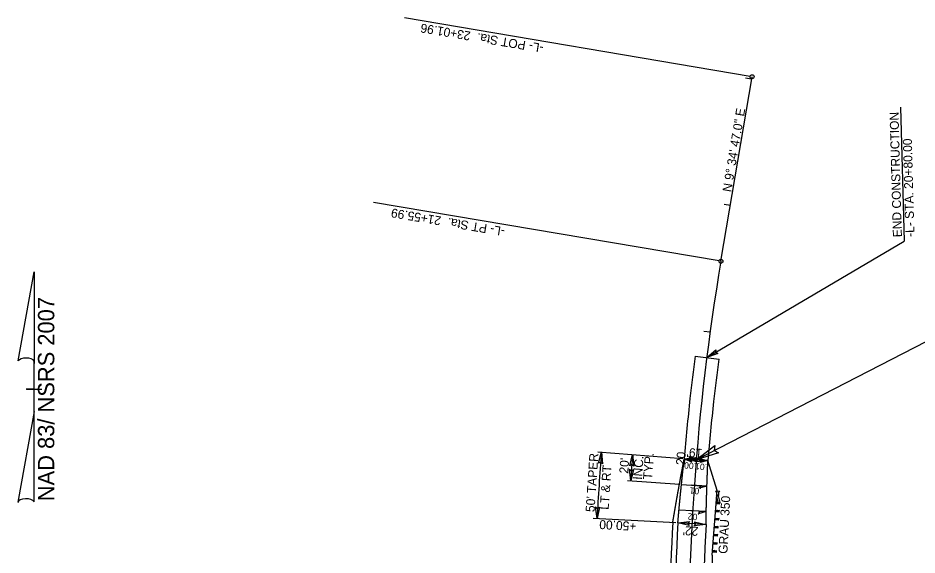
# Model space of a CAD drawing. Extents: x 1835351 to 1836442, y 993887 to 995358.
# Drawn here: x 1835358 to 1836059, y 994883 to 995302 of the extents above; entities that cross this region are included whole.
import ezdxf

# ---------------------------------------------------------------- set-up
doc = ezdxf.new("R2010")
doc.units = 0
for name, color, linetype in [('Prop Dimension', 7, 'Continuous'), ('Prop Dimension Text', 7, 'Continuous'), ('Prop EOT', 7, 'Continuous'), ('Prop Guardrail', 7, 'Continuous'), ('Prop Guardrail Anchor Unit CELL', 7, 'Continuous'), ('Prop Horizontal Alignment', 7, 'Continuous'), ('Prop Horizontal Alignment Direction Label', 7, 'Continuous'), ('Prop Horizontal Alignment Station Label', 7, 'Continuous'), ('Prop Horizontal Alignment Tick Label', 7, 'Continuous'), ('Prop Horizontal Alignment Tick Large', 7, 'Continuous'), ('Prop Horizontal Alignment Tick Small', 7, 'Continuous'), ('Prop Lane Lines', 7, 'Continuous'), ('Prop North Arrow NAD83 for Plan Sheets CELL', 7, 'Continuous'), ('Prop Paved Shoulder', 7, 'Continuous'), ('Prop Superelevation  Arrow CELL', 7, 'Continuous'), ('Prop Superelevation Label', 7, 'Continuous'), ('Prop Terminator CELL', 7, 'Continuous')]:
    doc.layers.add(name, color=color, linetype=linetype)

msp = doc.modelspace()

# ---------------------------------------------------------------- linework, layer by layer
at = {"layer": 'Prop Dimension'}
for p, q in [((1836046.57, 995232.25), (1836049.43, 995127.52)), ((1835895.31, 995036.81), (1836049.43, 995127.52)), ((1835810.24, 994963.48), (1835876.57, 994958.09)), ((1835877.74, 994958), (1835896.2, 994956.5)), ((1835833.43, 994940.95), (1835874.1, 994938.1)), ((1835871.15, 994908.03), (1835806.69, 994911.47)), ((1835894.7, 994906.77), (1835872.73, 994907.94))]:
    msp.add_line(p, q, dxfattribs=at)
for radius, end in [(1884.18, 176.94086), (1859.77, 175.99121)]:
    msp.add_arc((1837691.14, 994810.76), radius, 175.35811, end, dxfattribs=at)
at = {"layer": 'Prop Dimension Text'}
msp.add_line((1835887.07, 994957.24), (1836077.4, 995055.09), dxfattribs=at)
at = {"layer": 'Prop EOT'}
msp.add_line((1835886.28, 995037.95), (1835904.85, 995035.61), dxfattribs=at)
for radius in [1821, 1799]:
    msp.add_arc((1837691.14, 994810.76), radius, 176.94086, 181.53384, dxfattribs=at)
for centre, major_axis, ratio, start_param, end_param in [((1837192.63, 994942.7), (-342.09, -1896.88), 0.677504, 4.78411, 4.801345), ((1838782.69, 994796.91), (-746.07, -3717.17), 0.759534, 4.800145, 4.808919), ((1837641.28, 994819), (-1537.35, -877.61), 0.997858, 5.658085, 5.684815), ((1837572.45, 994795.61), (212.83, -1723.77), 0.968108, 4.473864, 4.500611)]:
    msp.add_ellipse(centre, major_axis=major_axis, ratio=ratio, start_param=start_param, end_param=end_param, dxfattribs=at)
for points in [[(1835872.73, 994907.94), (1835872.79, 994908.62), (1835872.85, 994909.3), (1835872.91, 994909.98), (1835872.97, 994910.65), (1835873.03, 994911.33), (1835873.09, 994912.01), (1835873.15, 994912.69), (1835873.21, 994913.36), (1835873.27, 994914.04), (1835873.33, 994914.72), (1835873.39, 994915.39), (1835873.45, 994916.07), (1835873.51, 994916.75), (1835873.57, 994917.43), (1835873.64, 994918.1), (1835873.7, 994918.78), (1835873.76, 994919.46), (1835873.82, 994920.13), (1835873.89, 994920.81), (1835873.95, 994921.49), (1835874.01, 994922.17), (1835874.08, 994922.84), (1835874.14, 994923.52), (1835874.21, 994924.2), (1835874.27, 994924.87), (1835874.33, 994925.55), (1835874.4, 994926.23), (1835874.46, 994926.9), (1835874.53, 994927.58), (1835874.6, 994928.26), (1835874.66, 994928.93), (1835874.73, 994929.61), (1835874.8, 994930.29), (1835874.86, 994930.96), (1835874.93, 994931.64), (1835875, 994932.32), (1835875.06, 994932.99), (1835875.13, 994933.67), (1835875.2, 994934.35), (1835875.27, 994935.02), (1835875.34, 994935.7), (1835875.41, 994936.38), (1835875.48, 994937.05), (1835875.54, 994937.73), (1835875.61, 994938.4), (1835875.68, 994939.08), (1835875.75, 994939.76), (1835875.82, 994940.43), (1835875.9, 994941.11), (1835875.97, 994941.78), (1835876.04, 994942.46), (1835876.11, 994943.14), (1835876.18, 994943.81), (1835876.25, 994944.49), (1835876.32, 994945.16), (1835876.4, 994945.84), (1835876.47, 994946.52), (1835876.54, 994947.19), (1835876.62, 994947.87), (1835876.69, 994948.54), (1835876.76, 994949.22), (1835876.84, 994949.89), (1835876.91, 994950.57), (1835876.99, 994951.25), (1835877.06, 994951.92), (1835877.13, 994952.6), (1835877.21, 994953.27), (1835877.29, 994953.95), (1835877.36, 994954.62), (1835877.44, 994955.3), (1835877.51, 994955.97), (1835877.59, 994956.65), (1835877.74, 994958)], [(1835894.7, 994906.77), (1835894.71, 994907.44), (1835894.72, 994908.11), (1835894.73, 994908.78), (1835894.75, 994909.46), (1835894.76, 994910.13), (1835894.77, 994910.8), (1835894.78, 994911.47), (1835894.79, 994912.14), (1835894.81, 994912.82), (1835894.82, 994913.49), (1835894.83, 994914.16), (1835894.85, 994914.83), (1835894.86, 994915.5), (1835894.88, 994916.18), (1835894.89, 994916.85), (1835894.91, 994917.52), (1835894.92, 994918.19), (1835894.94, 994918.86), (1835894.95, 994919.54), (1835894.97, 994920.21), (1835894.98, 994920.88), (1835895, 994921.55), (1835895.02, 994922.22), (1835895.03, 994922.9), (1835895.05, 994923.57), (1835895.07, 994924.24), (1835895.09, 994924.91), (1835895.1, 994925.58), (1835895.12, 994926.26), (1835895.14, 994926.93), (1835895.16, 994927.6), (1835895.18, 994928.27), (1835895.2, 994928.94), (1835895.22, 994929.62), (1835895.24, 994930.29), (1835895.26, 994930.96), (1835895.28, 994931.63), (1835895.3, 994932.31), (1835895.32, 994932.98), (1835895.34, 994933.65), (1835895.36, 994934.32), (1835895.38, 994934.99), (1835895.4, 994935.67), (1835895.42, 994936.34), (1835895.45, 994937.01), (1835895.47, 994937.68), (1835895.49, 994938.35), (1835895.51, 994939.03), (1835895.54, 994939.7), (1835895.56, 994940.37), (1835895.58, 994941.04), (1835895.61, 994941.71), (1835895.63, 994942.39), (1835895.66, 994943.06), (1835895.68, 994943.73), (1835895.71, 994944.4), (1835895.73, 994945.07), (1835895.76, 994945.75), (1835895.78, 994946.42), (1835895.81, 994947.09), (1835895.83, 994947.76), (1835895.86, 994948.44), (1835895.89, 994949.11), (1835895.91, 994949.78), (1835895.94, 994950.45), (1835895.97, 994951.12), (1835896, 994951.8), (1835896.02, 994952.47), (1835896.05, 994953.14), (1835896.08, 994953.81), (1835896.11, 994954.48), (1835896.14, 994955.16), (1835896.2, 994956.5)]]:
    msp.add_spline(points, degree=3, dxfattribs=at)
at = {"layer": 'Prop Guardrail'}
msp.add_arc((1837691.14, 994810.76), 1793, 177.69413, 180.25074, dxfattribs=at)
at = {"layer": 'Prop Guardrail Anchor Unit CELL'}
for p, q in [((1835899.59, 994882.9), (1835903.05, 994929.52)), ((1835903.24, 994931.6), (1835902.45, 994932.82)), ((1835902.45, 994932.82), (1835905.39, 994932.65)), ((1835904.59, 994929.91), (1835903.02, 994929.03)), ((1835903.02, 994929.03), (1835904.51, 994928.92)), ((1835904.18, 994924.03), (1835903.02, 994929.03)), ((1835903.09, 994930.02), (1835904.59, 994929.91)), ((1835903.09, 994930.02), (1835904.51, 994928.92)), ((1835903.13, 994929.55), (1835903.24, 994931.6)), ((1835903.74, 994929.52), (1835903.13, 994929.55)), ((1835904.35, 994929.48), (1835903.74, 994929.52)), ((1835904.46, 994931.53), (1835904.35, 994929.48)), ((1835905.39, 994932.65), (1835904.46, 994931.53)), ((1835904.51, 994928.92), (1835904.59, 994929.91)), ((1835904.51, 994928.92), (1835904.55, 994929.41)), ((1835905.71, 994923.91), (1835904.51, 994928.92)), ((1835902.58, 994923.14), (1835904.18, 994924.03)), ((1835902.58, 994923.14), (1835905.63, 994922.91)), ((1835902.65, 994924.14), (1835905.71, 994923.91)), ((1835904.11, 994923.03), (1835902.65, 994924.14)), ((1835904.11, 994923.03), (1835904.18, 994924.03)), ((1835905.71, 994923.91), (1835904.11, 994923.03)), ((1835904.18, 994924.03), (1835905.63, 994922.91)), ((1835905.63, 994922.91), (1835905.71, 994923.91)), ((1835902.11, 994916.86), (1835903.68, 994917.74)), ((1835902.11, 994916.86), (1835905.1, 994916.64)), ((1835902.19, 994917.85), (1835905.18, 994917.63)), ((1835903.61, 994916.75), (1835902.19, 994917.85)), ((1835903.61, 994916.75), (1835903.68, 994917.74)), ((1835905.18, 994917.63), (1835903.61, 994916.75)), ((1835903.68, 994917.74), (1835905.1, 994916.64)), ((1835905.1, 994916.64), (1835905.18, 994917.63)), ((1835901.64, 994910.57), (1835903.28, 994911.45)), ((1835901.64, 994910.57), (1835904.77, 994910.34)), ((1835901.72, 994911.57), (1835904.85, 994911.34)), ((1835903.21, 994910.46), (1835901.72, 994911.57)), ((1835903.21, 994910.46), (1835903.28, 994911.45)), ((1835904.85, 994911.34), (1835903.21, 994910.46)), ((1835903.28, 994911.45), (1835904.77, 994910.34)), ((1835904.77, 994910.34), (1835904.85, 994911.34)), ((1835901.18, 994904.29), (1835901.25, 994905.29)), ((1835901.18, 994904.29), (1835902.77, 994905.17)), ((1835901.18, 994904.29), (1835904.2, 994904.06)), ((1835901.25, 994905.29), (1835904.28, 994905.06)), ((1835902.69, 994904.18), (1835901.25, 994905.29)), ((1835902.69, 994904.18), (1835902.77, 994905.17)), ((1835904.28, 994905.06), (1835902.69, 994904.18)), ((1835902.77, 994905.17), (1835904.2, 994904.06)), ((1835904.2, 994904.06), (1835904.28, 994905.06)), ((1835900.71, 994898.01), (1835902.3, 994898.89)), ((1835900.71, 994898.01), (1835903.75, 994897.78)), ((1835900.78, 994899), (1835903.82, 994898.78)), ((1835902.23, 994897.89), (1835900.78, 994899)), ((1835902.23, 994897.89), (1835902.3, 994898.89)), ((1835903.82, 994898.78), (1835902.23, 994897.89)), ((1835902.3, 994898.89), (1835903.75, 994897.78)), ((1835903.75, 994897.78), (1835903.82, 994898.78)), ((1835899.78, 994885.44), (1835899.85, 994886.44)), ((1835901.35, 994886.32), (1835899.78, 994885.44)), ((1835899.85, 994886.44), (1835902.84, 994886.21)), ((1835899.85, 994886.44), (1835901.35, 994886.32)), ((1835901.27, 994885.33), (1835899.85, 994886.44)), ((1835900.24, 994891.72), (1835901.84, 994892.61)), ((1835900.24, 994891.72), (1835903.29, 994891.5)), ((1835900.32, 994892.72), (1835903.36, 994892.49)), ((1835901.77, 994891.61), (1835900.32, 994892.72)), ((1835901.27, 994885.33), (1835901.35, 994886.32)), ((1835902.84, 994886.21), (1835901.27, 994885.33)), ((1835901.35, 994886.32), (1835902.77, 994885.22)), ((1835901.77, 994891.61), (1835901.84, 994892.61)), ((1835903.36, 994892.49), (1835901.77, 994891.61)), ((1835901.84, 994892.61), (1835903.29, 994891.5)), ((1835902.77, 994885.22), (1835902.84, 994886.21)), ((1835903.29, 994891.5), (1835903.36, 994892.49)), ((1835899.78, 994885.44), (1835902.77, 994885.22))]:
    msp.add_line(p, q, dxfattribs=at)
at = {"layer": 'Prop Horizontal Alignment'}
msp.add_line((1835906.38, 995111.98), (1835930.67, 995255.92), dxfattribs=at)
msp.add_arc((1837691.14, 994810.76), 1810, 170.42027, 181.53384, dxfattribs=at)
at = {"layer": 'Prop Horizontal Alignment Station Label'}
for p, q in [((1835929.19, 995256.17), (1835659.5, 995301.69)), ((1835904.9, 995112.23), (1835635.21, 995157.75))]:
    msp.add_line(p, q, dxfattribs=at)
for centre in [(1835930.67, 995255.92), (1835906.38, 995111.98)]:
    msp.add_circle(centre, 1.5, dxfattribs=at)
at = {"layer": 'Prop Horizontal Alignment Tick Large'}
msp.add_line((1835887.07, 994957.24), (1835879.1, 994957.89), dxfattribs=at)
at = {"layer": 'Prop Horizontal Alignment Tick Small'}
for p, q in [((1835930.34, 995253.99), (1835925.41, 995254.82)), ((1835913.7, 995155.38), (1835908.77, 995156.21)), ((1835897.91, 995056.64), (1835892.96, 995057.32))]:
    msp.add_line(p, q, dxfattribs=at)
at = {"layer": 'Prop North Arrow NAD83 for Plan Sheets CELL'}
for p, q in [((1835357.9, 995034.31), (1835370.23, 995103.83)), ((1835370.3, 995103.83), (1835370.23, 995103.83)), ((1835370.3, 995103.83), (1835370.23, 995103.83)), ((1835370.3, 995103.83), (1835370.28, 995032.13)), ((1835370.26, 994994.93), (1835370.28, 995034.23)), ((1835370.28, 995032.13), (1835370.28, 995034.16)), ((1835364.27, 995012.33), (1835364.2, 995012.33)), ((1835369.6, 995012.33), (1835364.27, 995012.33)), ((1835364.35, 995012.33), (1835376.35, 995012.33)), ((1835370.26, 994994.93), (1835357.71, 994924.06)), ((1835370.31, 994924.36), (1835370.26, 994994.93))]:
    msp.add_line(p, q, dxfattribs=at)
for centre, start_param, end_param in [((1835364.11, 995033.56), 0.216388, 2.908219), ((1835364.07, 994923.81), 0.201328, 3.141593)]:
    msp.add_ellipse(centre, major_axis=(6.34, -0.05), ratio=0.461098, start_param=start_param, end_param=end_param, dxfattribs=at)
at = {"layer": 'Prop Paved Shoulder'}
for p, q in [((1835903.33, 994933.25), (1835896.2, 994956.5)), ((1835899.59, 994882.9), (1835903.33, 994933.25))]:
    msp.add_line(p, q, dxfattribs=at)
for centre, radius, start, end in [((1837691.14, 994810.76), 1825, 176.94086, 180.92604), ((1837680.42, 994810.95), 1782.29, 177.68644, 180.25842)]:
    msp.add_arc(centre, radius, start, end, dxfattribs=at)
msp.add_spline([(1835868.74, 994908.16), (1835868.85, 994908.83), (1835868.96, 994909.51), (1835869.07, 994910.18), (1835869.19, 994910.86), (1835869.3, 994911.54), (1835869.42, 994912.21), (1835869.53, 994912.89), (1835869.64, 994913.56), (1835869.76, 994914.24), (1835869.87, 994914.91), (1835869.99, 994915.59), (1835870.1, 994916.27), (1835870.22, 994916.94), (1835870.34, 994917.62), (1835870.45, 994918.29), (1835870.57, 994918.97), (1835870.68, 994919.64), (1835870.8, 994920.32), (1835870.92, 994920.99), (1835871.04, 994921.67), (1835871.15, 994922.34), (1835871.27, 994923.02), (1835871.39, 994923.69), (1835871.51, 994924.37), (1835871.63, 994925.04), (1835871.75, 994925.71), (1835871.86, 994926.39), (1835871.98, 994927.06), (1835872.1, 994927.74), (1835872.22, 994928.41), (1835872.34, 994929.09), (1835872.46, 994929.76), (1835872.58, 994930.43), (1835872.7, 994931.11), (1835872.83, 994931.78), (1835872.95, 994932.45), (1835873.07, 994933.13), (1835873.19, 994933.8), (1835873.31, 994934.47), (1835873.44, 994935.15), (1835873.56, 994935.82), (1835873.68, 994936.49), (1835873.8, 994937.17), (1835873.93, 994937.84), (1835874.05, 994938.51), (1835874.17, 994939.19), (1835874.3, 994939.86), (1835874.42, 994940.53), (1835874.55, 994941.21), (1835874.67, 994941.88), (1835874.8, 994942.55), (1835874.92, 994943.22), (1835875.05, 994943.9), (1835875.17, 994944.57), (1835875.3, 994945.24), (1835875.43, 994945.91), (1835875.55, 994946.58), (1835875.68, 994947.26), (1835875.81, 994947.93), (1835875.93, 994948.6), (1835876.06, 994949.27), (1835876.19, 994949.94), (1835876.32, 994950.62), (1835876.45, 994951.29), (1835876.57, 994951.96), (1835876.7, 994952.63), (1835876.83, 994953.3), (1835876.96, 994953.97), (1835877.09, 994954.64), (1835877.22, 994955.31), (1835877.35, 994955.99), (1835877.48, 994956.66), (1835877.74, 994958)], degree=3, dxfattribs=at)
at = {"layer": 'Prop Superelevation  Arrow CELL'}
for p, q in [((1835877.74, 994958), (1835889.7, 994957.03)), ((1835887.07, 994957.24), (1835877.74, 994958)), ((1835896.2, 994956.5), (1835884.24, 994957.47)), ((1835895.43, 994936.61), (1835883.46, 994937.45)), ((1835894.89, 994916.71), (1835882.91, 994917.42))]:
    msp.add_line(p, q, dxfattribs=at)
for points in [[(1835877.74, 994958), (1835883.56, 994955.52), (1835882.35, 994957.62)], [(1835887.07, 994957.24), (1835881.25, 994959.72), (1835882.46, 994957.62)], [(1835896.2, 994956.5), (1835890.06, 994954.99), (1835891.59, 994956.87)], [(1835895.43, 994936.61), (1835889.31, 994935.03), (1835890.82, 994936.93)], [(1835894.89, 994916.71), (1835888.78, 994915.07), (1835890.27, 994916.99)]]:
    msp.add_lwpolyline(points, close=True, dxfattribs=at)
at = {"layer": 'Prop Superelevation Label'}
for p, q in [((1835875.57, 994938), (1835895.43, 994936.61)), ((1835894.89, 994916.71), (1835873.62, 994917.97))]:
    msp.add_line(p, q, dxfattribs=at)
at = {"layer": 'Prop Terminator CELL'}
for points in [[(1835903.85, 995040.04), (1835895.31, 995036.81), (1835902.29, 995042.78), (1835902.11, 995040.82)], [(1835904.5, 994962.71), (1835887.07, 994957.24), (1835901.71, 994968.36), (1835901.12, 994964.46)], [(1835810.87, 994954.4), (1835813.14, 994963.24), (1835814, 994954.09), (1835812.5, 994955.37)], [(1835835.19, 994952.42), (1835837.46, 994961.27), (1835838.32, 994952.12), (1835836.82, 994953.4)], [(1835886.59, 994955.73), (1835877.74, 994958), (1835886.89, 994958.86), (1835885.62, 994957.36)], [(1835887.35, 994958.77), (1835896.2, 994956.5), (1835887.05, 994955.64), (1835888.32, 994957.14)], [(1835838.09, 994949.65), (1835835.91, 994940.78), (1835834.95, 994949.92), (1835836.46, 994948.66)], [(1835811.67, 994920.22), (1835809.64, 994911.31), (1835808.53, 994920.44), (1835810.06, 994919.2)], [(1835881.64, 994905.91), (1835872.73, 994907.94), (1835881.85, 994909.06), (1835880.62, 994907.52)], [(1835885.79, 994908.8), (1835894.7, 994906.77), (1835885.58, 994905.65), (1835886.81, 994907.19)]]:
    msp.add_lwpolyline(points, close=True, dxfattribs=at)

# ---------------------------------------------------------------- texts
at = {"layer": 'Prop Dimension Text'}
for s, rotation, p in [('END CONSTRUCTION', 91.56434, (1836047.63, 995130.81)), ('-L- STA. 20+80.00', 91.56434, (1836057.42, 995131.07)), ("50' TAPER", 86.14949, (1835807.67, 994916.21)), ("20'", 85.67466, (1835833.92, 994946.17)), ('INC.', 85.67466, (1835844.62, 994941.36)), ('TYP.', 85.67466, (1835852.52, 994941.54)), ('LT & RT', 86.14949, (1835818.68, 994918)), ('+50.00', 176.94086, (1835840.5, 994908.65))]:
    msp.add_text(s, height=7, rotation=rotation, dxfattribs=at).set_placement(p)
at = {"layer": 'Prop Guardrail Anchor Unit CELL'}
msp.add_text('GRAU 350', height=7, rotation=87.08342, dxfattribs=at).set_placement((1835911.36, 994883.69))
at = {"layer": 'Prop Horizontal Alignment Direction Label'}
msp.add_text('N 9%%d 34\' 47.0" E', height=7, rotation=80.42027, dxfattribs=at).set_placement((1835914.38, 995165.59))
at = {"layer": 'Prop Horizontal Alignment Station Label'}
for s, p in [('-L- POT Sta.  23+01.96', (1835768.28, 995281.3)), ('-L- PT Sta.  21+55.99', (1835738.12, 995138.35))]:
    msp.add_text(s, height=7, rotation=170.42027, dxfattribs=at).set_placement(p)
at = {"layer": 'Prop Horizontal Alignment Tick Label'}
msp.add_text('20', height=7, rotation=85.35811, dxfattribs=at).set_placement((1835878.19, 994952.76))
at = {"layer": 'Prop Lane Lines'}
for s, rotation, p in [('.00', 175.35811, (1835887.12, 994954.64)), ('.01', 175.35811, (1835895.7, 994953.86)), ('.01', 175.99121, (1835891.43, 994935.02)), ('.02', 176.62431, (1835889.96, 994914.86))]:
    msp.add_text(s, height=5, rotation=rotation, dxfattribs=at).set_placement(p)
at = {"layer": 'Prop North Arrow NAD83 for Plan Sheets CELL'}
msp.add_text('NAD 83/ NSRS 2007', height=12.75, rotation=89.97992, dxfattribs=at).set_placement((1835386.02, 994924.87))
at = {"layer": 'Prop Terminator CELL'}
for s, rotation, p in [("19'", 175.76789, (1835892.06, 994965.57)), ("22'", 176.94086, (1835888.92, 994904.76))]:
    msp.add_text(s, height=7, rotation=rotation, dxfattribs=at).set_placement(p)

doc.saveas('drawing.dxf')
